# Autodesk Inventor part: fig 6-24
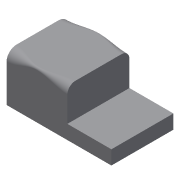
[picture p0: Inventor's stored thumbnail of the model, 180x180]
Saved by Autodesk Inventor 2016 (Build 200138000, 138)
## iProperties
Created: 2004-05
Part Number: fig 6-24
Document SubType Name: Modeling
Designer: CADCIM Technologies
Manufacturer: Standard
Standards Organization: Custom
Density: 1 g/cm^3
Material: Generic
Appearance: Default
Author: CADCIM Technologies
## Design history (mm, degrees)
node "Sketch1"
sketch "Sketch2"
  geometry: L1 (0.098, 47.711)-(0.098, 0.049); L2 (0.098, 0.049)-(-105.483, 0.049); L3 (-105.483, 0.049)-(-105.483, 14.192); L4 (-105.483, 14.192)-(-61.139, 14.192); L5 (-61.139, 14.192)-(-61.139, 47.711); L6 (-61.139, 47.711)-(0.098, 47.711)
  constraints: 12 end point, 3 parallel, 2 perpendicular, 1 vertical
extrude "Extrusion1" new body sketch "Sketch2" stored distance "d0" = 62.5; taper "d1" = 0 deg
fillet "Fillet9" dims "d61" = 10, "d62" = 8, "d63" = 2, "d64" = 5
fillet "Fillet10" dims "d65" = 8, "d66" = 10, "d67" = 2, "d68" = 5
body "Solid1"
